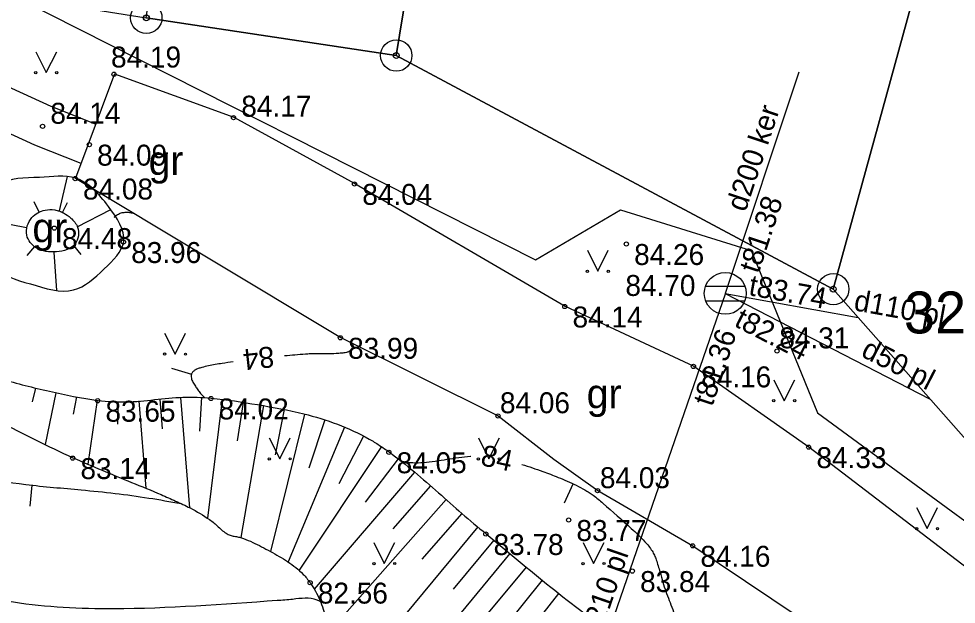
# Model space of a CAD drawing. Extents: x 576692 to 577659, y 273254 to 273799.
# Drawn here: x 577156.27 to 577178.67, y 273464.03 to 273478.01 of the extents above; entities that cross this region are included whole.
import ezdxf

# ---------------------------------------------------------------- set-up
doc = ezdxf.new("R2010")
doc.units = 0
for name, color, linetype in [('BUVE_EKAS_BPAL_####_#', 7, 'Continuous'), ('BUVE_EKAS_RAKS_TKST_#', 7, 'Continuous'), ('CELI_CAPM_####_####_#', 7, 'Continuous'), ('CELI_CMAL_####_####_#', 7, 'Continuous'), ('CELI_TAKA_####_####_#', 7, 'Continuous'), ('ELEK_ELEM_####_####_#', 7, 'Continuous'), ('ELEK_VADP_ZSPR_####_#', 7, 'Continuous'), ('GAZE_ELEM_####_####_#', 7, 'Continuous'), ('GEOD_ELEM_####_TKST_#', 7, 'Continuous'), ('GEOD_SITP_####_TKST_#', 7, 'Continuous'), ('HIDT_REZV_####_TKST_#', 7, 'Continuous'), ('Level 50', 7, 'Continuous'), ('LKAN_ELEM_PAST_TKST_#', 7, 'Continuous'), ('RELJ_ELEM_####_####_#', 7, 'Continuous'), ('RELJ_HORZ_PAMT_####_#', 7, 'Continuous'), ('RELJ_HORZ_RESN_####_#', 7, 'Continuous'), ('ROBZ_IERR_####_TKST_#', 7, 'Continuous'), ('SAKK_KKAN_####_####_#', 7, 'Continuous'), ('SAKT_ELEM_####_####_#', 7, 'Continuous'), ('SILT_VADP_UDEN_####_#', 7, 'Continuous'), ('TERT_IZMT_####_TKST_#', 7, 'Continuous'), ('UDTK_VADP_UDEN_####_#', 7, 'Continuous')]:
    doc.layers.add(name, color=color, linetype=linetype)

msp = doc.modelspace()

# ---------------------------------------------------------------- linework, layer by layer
at = {"layer": 'BUVE_EKAS_RAKS_TKST_#'}
for centre, radius in [((577159.313, 273478.03), 0.375), ((577159.313, 273478.03), 0.0702), ((577165.286, 273477.13), 0.375), ((577165.286, 273477.13), 0.0702), ((577175.727, 273471.552), 0.375), ((577175.727, 273471.552), 0.0702)]:
    msp.add_circle(centre, radius, dxfattribs=at)
at = {"layer": 'CELI_CAPM_####_####_#'}
for points in [[(577158.55, 273476.693), (577157.623, 273474.202)], [(577158.55, 273476.693), (577161.406, 273475.656), (577164.295, 273474.073), (577169.32, 273471.145), (577172.393, 273469.714), (577175.147, 273467.785), (577178.935, 273464.89), (577184.057, 273460.941), (577186.5, 273459.556), (577191.374, 273457.455), (577198.177, 273454.97), (577205.318, 273452.374), (577208.015, 273451.696), (577209.372, 273451.747), (577211.65, 273452.511), (577213.993, 273455.077), (577214.876, 273457.104), (577212.594, 273458.417)], [(577157.623, 273474.202), (577163.958, 273470.399), (577167.719, 273468.527), (577169.054, 273467.493), (577170.102, 273466.747), (577172.369, 273465.426), (577176.147, 273462.888), (577182.512, 273458.828), (577188.805, 273455.639), (577196.247, 273452.706), (577201.737, 273450.493), (577204.433, 273449.512), (577207.868, 273448.574)]]:
    msp.add_lwpolyline(points, dxfattribs=at)
at = {"layer": 'CELI_TAKA_####_####_#'}
msp.add_lwpolyline([(577034.918, 273498.457), (577056.159, 273496.649), (577089.41, 273495.849), (577091.53, 273498.895), (577133.743, 273488.404), (577156.263, 273478.496), (577168.613, 273472.255), (577170.64, 273473.445), (577173.767, 273472.475), (577175.353, 273468.597), (577186.541, 273460.401)], dxfattribs=at)
at = {"layer": 'ELEK_ELEM_####_####_#'}
for points in [[(577158.103, 273475.492), (577157.04, 273475.911), (577154.123, 273477.245)], [(577157.754, 273474.555), (577156.648, 273474.991), (577153.707, 273476.335)]]:
    msp.add_lwpolyline(points, dxfattribs=at)
at = {"layer": 'ELEK_VADP_ZSPR_####_#'}
msp.add_lwpolyline([(577173.146, 273471.451), (577178.046, 273468.927)], dxfattribs=at)
at = {"layer": 'GAZE_ELEM_####_####_#'}
for p, q in [((577157.238, 273473.418), (577157.427, 273474.243)), ((577156.751, 273473.392), (577156.63, 273473.639)), ((577157.312, 273473.382), (577157.427, 273473.62)), ((577157.665, 273473.042), (577158.463, 273473.454)), ((577156.452, 273473.012), (577155.412, 273473.224)), ((577156.638, 273472.574), (577156.455, 273472.352)), ((577157.571, 273472.594), (577157.746, 273472.382)), ((577157.105, 273472.438), (577157.166, 273471.516)), ((577156.668, 273469.19), (577156.589, 273468.858)), ((577157.155, 273469.079), (577156.893, 273467.843)), ((577157.645, 273468.981), (577157.569, 273468.569)), ((577158.139, 273468.9), (577157.913, 273467.372)), ((577159.634, 273468.923), (577159.694, 273468.218)), ((577160.132, 273468.967), (577160.347, 273466.333)), ((577160.631, 273468.97), (577160.584, 273468.16)), ((577161.128, 273468.919), (577160.772, 273466.082)), ((577158.636, 273468.854), (577158.626, 273468.324)), ((577159.135, 273468.882), (577159.299, 273466.801)), ((577161.624, 273468.849), (577161.484, 273467.93)), ((577162.117, 273468.77), (577161.57, 273465.62)), ((577162.609, 273468.678), (577162.391, 273467.594)), ((577163.097, 273468.569), (577162.281, 273465.288)), ((577164.045, 273468.256), (577162.701, 273465.038)), ((577163.577, 273468.43), (577163.193, 273467.277)), ((577164.499, 273468.045), (577163.915, 273466.905)), ((577164.93, 273467.793), (577162.962, 273464.84)), ((577165.334, 273467.498), (577164.54, 273466.465)), ((577165.723, 273467.184), (577163.327, 273464.388)), ((577166.102, 273466.858), (577165.202, 273465.826)), ((577166.477, 273466.528), (577163.672, 273463.364)), ((577166.852, 273466.197), (577165.895, 273465.106)), ((577167.234, 273465.875), (577164.048, 273462.038)), ((577167.619, 273465.556), (577166.646, 273464.386)), ((577168.003, 273465.236), (577164.729, 273461.298)), ((577168.388, 273464.917), (577167.405, 273463.724)), ((577168.775, 273464.6), (577165.525, 273460.589)), ((577169.165, 273464.287), (577168.21, 273463.075))]:
    msp.add_line(p, q, dxfattribs=at)
for points in [[(577157.238, 273473.418), (577157.124, 273473.444), (577156.893, 273473.44), (577156.58, 273473.259), (577156.457, 273472.842), (577156.684, 273472.538), (577157.168, 273472.443), (577157.614, 273472.633), (577157.671, 273473.031), (577157.51, 273473.25), (577157.333, 273473.372), (577157.238, 273473.418)], [(577150.292, 273472.995), (577153.747, 273470.424), (577154.232, 273470.105), (577154.486, 273469.963), (577154.747, 273469.83), (577155.288, 273469.595), (577155.845, 273469.409), (577156.997, 273469.114), (577158.159, 273468.897), (577158.831, 273468.859), (577159.51, 273468.913), (577160.189, 273468.971), (577160.863, 273468.95), (577161.973, 273468.794), (577163.076, 273468.574), (577164.638, 273467.972), (577164.88, 273467.826), (577165.115, 273467.664), (577165.721, 273467.186), (577166.293, 273466.691), (577166.855, 273466.195), (577167.431, 273465.712), (577168.975, 273464.439), (577169.766, 273463.827), (577170.171, 273463.533), (577170.584, 273463.25), (577171.08, 273462.944), (577171.587, 273462.656), (577172.212, 273462.304)]]:
    msp.add_spline(points, degree=3, dxfattribs=at)
at = {"layer": 'GEOD_ELEM_####_TKST_#'}
for p, q in [((577159.915, 273469.666), (577160.393, 273469.518)), ((577169.303, 273466.448), (577169.513, 273466.902))]:
    msp.add_line(p, q, dxfattribs=at)
for points in [[(577158.548, 273473.267), (577158.555, 273473.278), (577158.578, 273473.298), (577158.601, 273473.316), (577158.647, 273473.344), (577158.74, 273473.379), (577158.788, 273473.386), (577158.836, 273473.389), (577158.932, 273473.38), (577159.021, 273473.359)], [(577141.558, 273470.392), (577143.275, 273468.884), (577144.24, 273467.987), (577144.897, 273467.365), (577145.703, 273466.615), (577146.112, 273466.246), (577146.527, 273465.883), (577147.182, 273465.358), (577147.86, 273464.861), (577148.893, 273464.133), (577149.943, 273463.436), (577151.012, 273462.766), (577152.106, 273462.121), (577152.761, 273461.841), (577154.381, 273461.474), (577156.403, 273461.078), (577157.416, 273460.903), (577157.924, 273460.825), (577158.432, 273460.755), (577159.182, 273460.744)], [(577164.259, 273470.226), (577164.202, 273470.108), (577164.155, 273470.064), (577164.128, 273470.049), (577164.098, 273470.04), (577163.975, 273470.023), (577163.852, 273470.014), (577163.606, 273470.008), (577163.36, 273470.009), (577163.237, 273470.006), (577163.114, 273469.998), (577162.865, 273469.977), (577162.617, 273469.958)], [(577161.391, 273469.82), (577161.126, 273469.778), (577160.799, 273469.722), (577160.637, 273469.68), (577160.596, 273469.669), (577160.556, 273469.656), (577160.516, 273469.64), (577160.496, 273469.631), (577160.476, 273469.62), (577160.419, 273469.569), (577160.4, 273469.538), (577160.393, 273469.521), (577160.389, 273469.504), (577160.396, 273469.405), (577160.441, 273469.308), (577160.5, 273469.215), (577160.561, 273469.126), (577160.626, 273469.043), (577160.7, 273468.966)], [(577165.432, 273467.421), (577165.934, 273467.413), (577166.497, 273467.491), (577167.06, 273467.565), (577167.068, 273467.566)], [(577168.286, 273467.365), (577168.787, 273467.2), (577169.153, 273467.058), (577169.584, 273466.868), (577169.792, 273466.759), (577169.893, 273466.698), (577169.99, 273466.631), (577170.11, 273466.537), (577170.226, 273466.437), (577170.901, 273465.839), (577171.225, 273465.522), (577171.399, 273465.301), (577171.428, 273465.25), (577171.455, 273465.198), (577171.497, 273465.09), (577171.542, 273464.945), (577171.588, 273464.798), (577171.622, 273464.676), (577171.689, 273464.443), (577171.766, 273464.231), (577171.937, 273463.794), (577172.022, 273463.62), (577172.121, 273463.453), (577172.336, 273463.13), (577172.636, 273462.698), (577172.943, 273462.28), (577173.105, 273462.078), (577173.276, 273461.884), (577173.645, 273461.524), (577173.663, 273461.508)]]:
    msp.add_spline(points, degree=3, dxfattribs=at)
at = {"layer": 'GEOD_SITP_####_TKST_#'}
msp.add_line((577156.537, 273466.374), (577156.589, 273466.871), dxfattribs=at)
for points in [[(577163.475, 273464.089), (577163.392, 273464.129), (577162.81, 273464.145), (577162.439, 273464.115), (577158.532, 273463.917), (577156.138, 273464.075), (577153.684, 273464.688), (577150.17, 273466.317), (577149.864, 273466.517), (577147.276, 273468.521), (577146.935, 273468.792), (577145.588, 273469.801), (577145.044, 273470.233), (577144.104, 273471.042), (577143.19, 273471.88), (577142.278, 273472.721), (577141.344, 273473.538), (577140.623, 273474.077), (577137.357, 273476.061), (577136.928, 273476.301), (577132.316, 273478.796), (577131.9, 273479.063), (577131.356, 273479.37), (577130.377, 273479.771), (577128.277, 273480.754), (577126.871, 273481.501), (577124.545, 273482.868), (577123.178, 273483.762)], [(577166.593, 273458.696), (577165.187, 273458.059), (577164.875, 273457.922), (577164.491, 273457.686), (577162.302, 273456.206), (577161.764, 273455.814), (577161.241, 273455.404), (577160.714, 273454.993), (577160.167, 273454.598), (577159.999, 273454.535), (577159.027, 273454.496), (577158.048, 273454.538), (577156.101, 273454.798), (577152.661, 273455.553), (577151.532, 273455.993), (577149.986, 273456.781), (577148.844, 273457.51), (577147.363, 273458.633), (577145.534, 273460.051), (577143.944, 273461.193), (577142.042, 273462.468), (577141.403, 273463.057), (577140.837, 273463.635), (577140.109, 273464.326), (577139.369, 273465.003), (577138.633, 273465.685), (577137.916, 273466.387), (577135.558, 273468.862), (577134.554, 273469.941), (577133.743, 273470.594), (577132.927, 273471.093), (577132.09, 273471.541), (577130.345, 273472.284), (577126.974, 273473.303), (577125.586, 273473.592), (577124.552, 273473.748), (577123.809, 273473.891), (577123.074, 273474.065), (577122.344, 273474.266), (577121.616, 273474.49), (577120.793, 273474.8), (577120.01, 273475.188), (577119.266, 273475.658), (577118.562, 273476.212), (577118.146, 273476.63), (577117.803, 273477.098), (577117.412, 273477.762), (577117.057, 273478.443), (577116.7, 273479.122), (577116.302, 273479.778), (577115.362, 273480.971), (577114.89, 273481.472), (577114.397, 273481.946), (577113.314, 273482.777)], [(577116.718, 273482.791), (577117.713, 273481.669), (577118.173, 273481.03), (577118.411, 273480.724), (577119.802, 273479.118), (577121.752, 273477.119), (577122.759, 273476.6), (577123.644, 273476.442), (577124.533, 273476.323), (577125.422, 273476.207), (577126.304, 273476.056), (577127.087, 273475.883), (577130.622, 273474.787), (577132.555, 273473.943), (577135.449, 273472.171), (577138.246, 273470.067), (577138.873, 273469.574), (577139.741, 273468.832), (577143.264, 273465.458), (577145.724, 273463.184), (577145.753, 273463.158), (577145.777, 273463.14), (577145.886, 273463.067), (577150.181, 273460.014), (577152.17, 273458.77), (577153.669, 273458.083), (577154.453, 273457.826), (577155.261, 273457.612), (577156.215, 273457.455), (577157.17, 273457.403), (577158.983, 273457.442), (577160.796, 273457.745), (577161.304, 273457.959), (577161.892, 273458.317), (577162.457, 273458.705), (577163.022, 273459.092), (577163.614, 273459.447), (577164.516, 273459.794), (577166.385, 273459.968)], [(577129.677, 273482.472), (577132.59, 273481.324), (577134.5, 273480.245), (577134.815, 273480.009), (577135.12, 273479.761), (577135.426, 273479.514), (577135.74, 273479.279), (577137.737, 273477.934), (577139.646, 273476.77), (577141.258, 273475.695), (577144.074, 273473.557), (577145.726, 273472.249), (577147.182, 273471.237), (577147.822, 273470.775), (577148.324, 273470.363), (577149.251, 273469.681), (577151.065, 273468.586), (577152.66, 273467.808), (577153.965, 273467.377), (577156.433, 273466.888), (577157.76, 273466.759), (577159.37, 273466.565), (577160.143, 273466.433)], [(577106.474, 273482.143), (577107.273, 273480.985), (577107.845, 273480.069), (577108.402, 273479.439), (577108.828, 273479.037), (577109.274, 273478.658), (577109.721, 273478.277), (577110.147, 273477.869), (577111.449, 273475.985), (577112.725, 273472.403), (577112.739, 273472.366), (577112.777, 273472.312), (577113.643, 273471.348), (577114.534, 273470.423), (577116.474, 273468.746), (577117.101, 273468.338), (577117.749, 273467.987), (577119.117, 273467.482), (577120.858, 273467.06), (577122.179, 273466.717), (577123.841, 273466.173), (577126.598, 273465.044), (577129.123, 273463.961), (577129.672, 273463.618), (577131.325, 273462.015), (577134.637, 273458.373), (577135.217, 273457.746), (577135.419, 273457.563), (577136.047, 273457.079), (577139.812, 273454.454), (577144.45, 273451.73), (577144.793, 273451.535), (577146.497, 273450.623), (577150.254, 273448.954), (577152.697, 273447.984), (577153.775, 273447.74), (577155.236, 273447.728), (577159.322, 273448.233), (577161.712, 273449.142), (577162.387, 273449.581), (577163.045, 273450.037), (577164.372, 273450.926), (577164.429, 273450.961), (577164.481, 273450.994), (577164.707, 273451.169), (577166.074, 273452.46), (577166.075, 273452.462)], [(577103.941, 273481.574), (577104.781, 273481.346), (577105.369, 273481.098), (577105.925, 273480.75), (577106.523, 273480.199), (577107.027, 273479.582), (577108.252, 273477.888), (577108.311, 273477.79), (577108.711, 273477.013), (577109.989, 273474.739), (577110.74, 273472.971), (577112.057, 273470.273), (577114.672, 273466.892), (577115.343, 273466.208), (577115.874, 273465.879), (577116.771, 273465.613), (577118.526, 273465.269), (577119.403, 273465.1), (577120.277, 273464.914), (577121.504, 273464.603), (577123.282, 273464.013), (577124.073, 273463.706), (577125.261, 273463.182), (577128.324, 273461.448), (577130.236, 273459.87), (577130.502, 273459.597), (577130.943, 273459.112), (577134.397, 273455.602), (577138.548, 273452.162), (577138.644, 273452.094), (577138.693, 273452.065), (577141.998, 273450.387), (577144.104, 273449.301), (577144.408, 273449.14), (577148.783, 273446.928), (577149.827, 273446.456), (577150.456, 273446.206), (577152.816, 273445.347), (577154.026, 273444.984), (577154.676, 273444.909), (577154.966, 273444.913), (577157.556, 273444.937), (577159.522, 273444.973), (577160.037, 273445.163), (577160.747, 273445.6), (577161.429, 273446.055), (577162.713, 273447.059), (577163.535, 273447.804), (577164.763, 273448.988), (577165.391, 273449.452), (577166.068, 273449.815), (577166.577, 273450.265), (577166.614, 273450.33)]]:
    msp.add_spline(points, degree=3, dxfattribs=at)
at = {"layer": 'Level 50'}
for points in [[(577174.906, 273476.734), (577173.146, 273471.451)], [(577173.153, 273471.458), (577168.123, 273456.916)], [(577173.146, 273471.451), (577176.325, 273470.875)]]:
    msp.add_lwpolyline(points, dxfattribs=at)
at = {"layer": 'LKAN_ELEM_PAST_TKST_#'}
for p, q in [((577156.672, 273477.222), (577156.922, 273476.722)), ((577156.922, 273476.722), (577157.172, 273477.222)), ((577169.852, 273472.479), (577170.102, 273471.979)), ((577170.102, 273471.979), (577170.352, 273472.479)), ((577159.75, 273470.5), (577160, 273470)), ((577160, 273470), (577160.25, 273470.5)), ((577174.306, 273469.389), (577174.556, 273468.889)), ((577174.556, 273468.889), (577174.806, 273469.389)), ((577162.25, 273468), (577162.5, 273467.5)), ((577162.5, 273467.5), (577162.75, 273468)), ((577167.25, 273468), (577167.5, 273467.5)), ((577167.5, 273467.5), (577167.75, 273468)), ((577177.718, 273466.335), (577177.968, 273465.835)), ((577177.968, 273465.835), (577178.218, 273466.335)), ((577164.75, 273465.5), (577165, 273465)), ((577165, 273465), (577165.25, 273465.5)), ((577169.75, 273465.5), (577170, 273465)), ((577170, 273465), (577170.25, 273465.5))]:
    msp.add_line(p, q, dxfattribs=at)
for centre, radius in [((577156.672, 273476.722), 0.028), ((577157.172, 273476.722), 0.0263), ((577169.852, 273471.979), 0.028), ((577170.352, 273471.979), 0.0263), ((577159.75, 273470), 0.028), ((577160.25, 273470), 0.0263), ((577174.306, 273468.889), 0.028), ((577174.806, 273468.889), 0.0263), ((577162.25, 273467.5), 0.028), ((577162.75, 273467.5), 0.0263), ((577167.25, 273467.5), 0.028), ((577167.75, 273467.5), 0.0263), ((577177.717, 273465.835), 0.028), ((577178.217, 273465.835), 0.0263), ((577164.75, 273465), 0.028), ((577165.25, 273465), 0.0263), ((577169.75, 273465), 0.028), ((577170.25, 273465), 0.0263)]:
    msp.add_circle(centre, radius, dxfattribs=at)
at = {"layer": 'RELJ_ELEM_####_####_#'}
for centre in [(577158.541, 273476.683), (577161.397, 273475.646), (577156.835, 273475.44), (577157.952, 273475.001), (577157.615, 273474.192), (577164.288, 273474.064), (577157.114, 273473.009), (577158.766, 273472.676), (577170.784, 273472.629), (577169.312, 273471.137), (577163.95, 273470.39), (577174.382, 273470.075), (577172.386, 273469.707), (577158.152, 273468.887), (577160.856, 273468.941), (577167.718, 273468.524), (577175.14, 273467.779), (577157.554, 273467.517), (577165.109, 273467.656), (577170.096, 273466.739), (577169.405, 273466.039), (577167.425, 273465.704), (577172.367, 273465.423), (577170.926, 273464.82), (577163.227, 273464.544)]:
    msp.add_circle(centre, 0.05, dxfattribs=at)
at = {"layer": 'SAKT_ELEM_####_####_#'}
for points in [[(577155.479, 273473.656), (577155.798, 273474.038), (577156.759, 273474.221), (577157.623, 273474.202), (577158.407, 273473.528), (577158.774, 273472.686), (577158.309, 273472.036), (577157.576, 273471.532), (577156.543, 273471.676), (577155.628, 273472.114), (577155.366, 273472.926), (577155.479, 273473.656)], [(577148.953, 273471.195), (577149.404, 273470.938), (577149.828, 273470.697), (577151.645, 273469.662), (577151.914, 273469.545), (577152.201, 273469.477), (577152.806, 273469.43), (577153.417, 273469.396), (577153.992, 273469.251), (577154.89, 273468.833), (577155.779, 273468.394), (577156.667, 273467.953), (577157.561, 273467.528), (577158.258, 273467.227), (577158.962, 273466.939), (577159.665, 273466.646), (577160.014, 273466.491), (577160.36, 273466.327), (577160.825, 273466.048), (577160.933, 273465.967), (577161.034, 273465.875), (577161.136, 273465.785), (577161.247, 273465.708), (577161.341, 273465.67), (577161.441, 273465.647), (577161.542, 273465.627), (577161.639, 273465.597), (577162.067, 273465.4), (577162.484, 273465.172), (577162.885, 273464.904), (577163.064, 273464.742), (577163.148, 273464.648), (577163.227, 273464.544), (577163.459, 273464.127), (577163.602, 273463.695), (577163.691, 273463.254), (577163.759, 273462.809), (577163.755, 273462.717), (577163.735, 273462.623), (577163.722, 273462.53), (577163.743, 273462.444), (577164.045, 273462.042), (577164.375, 273461.66), (577164.729, 273461.298), (577165.525, 273460.589), (577166.488, 273459.924), (577167.162, 273459.626)]]:
    msp.add_spline(points, degree=3, dxfattribs=at)
at = {"layer": 'SILT_VADP_UDEN_####_#'}
for points in [[(577101.419, 273503.013), (577097.198, 273494.389), (577104.253, 273493.035), (577126.908, 273488.584), (577129.873, 273499.999), (577136.711, 273491.012), (577145.743, 273485.823), (577154.748, 273478.761), (577159.313, 273478.03), (577165.286, 273477.13), (577175.727, 273471.552), (577185.907, 273460.029), (577209.478, 273451.452), (577215.373, 273452.58), (577215.241, 273457.197), (577215.048, 273463.213), (577214.516, 273473.767)], [(577101.419, 273503.013), (577097.198, 273494.389), (577104.253, 273493.035), (577126.908, 273488.584), (577129.873, 273499.999), (577136.711, 273491.012), (577145.743, 273485.823), (577154.748, 273478.761), (577159.313, 273478.03), (577165.286, 273477.13), (577175.727, 273471.552), (577185.907, 273460.029), (577209.478, 273451.452), (577215.373, 273452.58), (577215.241, 273457.197), (577215.048, 273463.213), (577214.516, 273473.767)], [(577166.781, 273486.263), (577165.286, 273477.13), (577159.313, 273478.03), (577160.257, 273484.135), (577160.398, 273485.032), (577155.885, 273485.725), (577156.141, 273490.5)], [(577178.175, 273480.48), (577175.727, 273471.552), (577165.286, 273477.13), (577166.781, 273486.263)], [(577187.202, 273470.658), (577185.907, 273460.029), (577175.727, 273471.552), (577178.175, 273480.48)]]:
    msp.add_lwpolyline(points, dxfattribs=at)
at = {"layer": 'UDTK_VADP_UDEN_####_#'}
for p, q in [((577172.678, 273471.626), (577173.614, 273471.626)), ((577172.678, 273471.276), (577173.614, 273471.276))]:
    msp.add_line(p, q, dxfattribs=at)
msp.add_circle((577173.146, 273471.451), 0.5, dxfattribs=at)

# ---------------------------------------------------------------- texts
at = {"layer": 'BUVE_EKAS_BPAL_####_#'}
msp.add_text('32010020140', height=1, dxfattribs=at).set_placement((577177.415, 273470.495))
at = {"layer": 'CELI_CMAL_####_####_#'}
for p in [(577159.369, 273474.278), (577169.836, 273468.708)]:
    msp.add_text('gr', height=0.7, dxfattribs=at).set_placement(p)
at = {"layer": 'HIDT_REZV_####_TKST_#'}
for s, p in [(' 84.19', (577158.285, 273476.844)), (' 84.17', (577161.397, 273475.67)), (' 84.14', (577156.835, 273475.501)), (' 84.09', (577157.952, 273474.501)), (' 84.08', (577157.615, 273473.692)), (' 84.04', (577164.288, 273473.564)), (' 84.48', (577157.114, 273472.509)), (' 83.96', (577158.766, 273472.176)), (' 84.26', (577170.784, 273472.129)), (' 84.14', (577169.312, 273470.637)), (' 84.31', (577174.252, 273470.139)), (' 83.99', (577163.95, 273469.89)), (' 84.16', (577172.386, 273469.207)), (' 83.65', (577158.152, 273468.387)), (' 84.02', (577160.856, 273468.441)), (' 84.06', (577167.577, 273468.589)), (' 84.33', (577175.14, 273467.279)), (' 84.05', (577165.109, 273467.156)), (' 83.14', (577157.554, 273467.017)), (' 84.03', (577169.966, 273466.8)), (' 83.77', (577169.405, 273465.539)), (' 83.78', (577167.425, 273465.204)), (' 84.16', (577172.367, 273464.923)), (' 83.84', (577170.926, 273464.32)), (' 82.56', (577163.227, 273464.044))]:
    msp.add_text(s, height=0.5, dxfattribs=at).set_placement(p)
at = {"layer": 'RELJ_HORZ_PAMT_####_#'}
for rotation, p in [(186.2113, (577162.34, 273470.191)), (347.671, (577167.277, 273467.355))]:
    msp.add_text('84', height=0.5, rotation=rotation, dxfattribs=at).set_placement(p)
at = {"layer": 'RELJ_HORZ_RESN_####_#'}
msp.add_text('gr', height=0.7, dxfattribs=at).set_placement((577156.592, 273472.671))
at = {"layer": 'ROBZ_IERR_####_TKST_#'}
for s, p in [('t82.24', (577173.334, 273470.683)), ('d50 pl', (577176.364, 273469.962))]:
    msp.add_text(s, height=0.5, rotation=332.7489, dxfattribs=at).set_placement(p)
at = {"layer": 'SAKK_KKAN_####_####_#'}
msp.add_text('84.70', height=0.5, dxfattribs=at).set_placement((577170.761, 273471.39))
at = {"layer": 'TERT_IZMT_####_TKST_#'}
for s, rotation, p in [('d200 ker', 71.5721, (577173.63, 273473.377)), ('t81.38', 71.5721, (577173.941, 273471.906)), ('t83.74', 349.7286, (577173.687, 273471.411)), ('d110 pl', 349.7286, (577176.199, 273471.05)), ('t81.36', 71.5721, (577172.836, 273468.73)), ('d210 pl', 70.9198, (577170.127, 273463.169))]:
    msp.add_text(s, height=0.5, rotation=rotation, dxfattribs=at).set_placement(p)

doc.saveas('drawing.dxf')
